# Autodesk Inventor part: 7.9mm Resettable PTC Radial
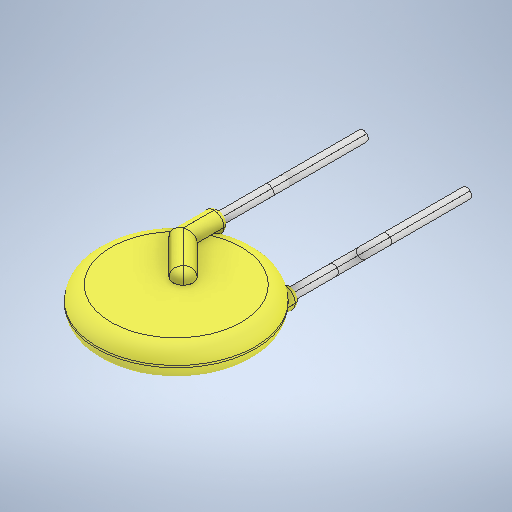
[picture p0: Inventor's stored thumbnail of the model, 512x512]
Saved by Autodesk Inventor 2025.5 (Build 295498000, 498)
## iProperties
Created: 2020-03
Part Number: 7.9mm Resettable PTC Radial
Material: Genérico
Description: FreeCAD Model
Document SubType Name: Modeling
Designer: Luis M
Authority: Unknown
Density: 1 g/cm^3
Appearance: Valor por defecto
Title: D:/Altium Board/Parts/CAD Models/Resettable Fuse/Radial/7.9mm Resettable PTC Radial.step
Author: Author
Sending System: FreeCAD
Preprocessor: Open CASCADE STEP processor 7.3
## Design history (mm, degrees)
feature "Base1"
node "Sólido1"
